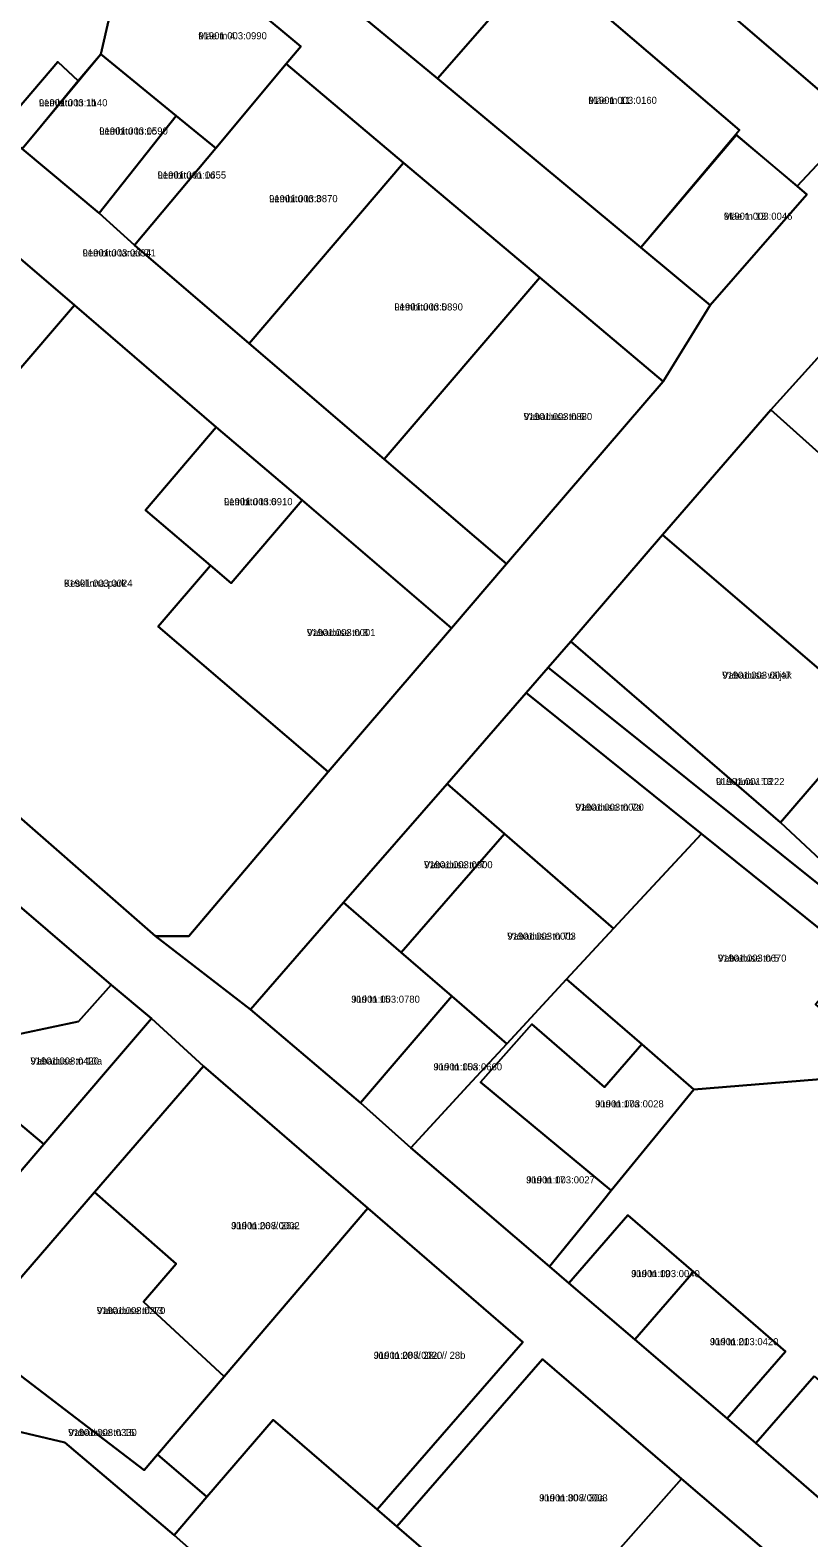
# Model space of a CAD drawing. Extents: x 675810 to 681273, y 6411190 to 6417565.
# Drawn here: x 677993.2 to 678158, y 6415458.6 to 6415777.9 of the extents above; entities that cross this region are included whole.
import ezdxf

# ---------------------------------------------------------------- set-up
doc = ezdxf.new("R2010")
doc.units = 0
for name, color, linetype in [('L_AADRESS', 7, 'Continuous'), ('PIIR', 7, 'Continuous'), ('TUNNUS', 7, 'Continuous')]:
    doc.layers.add(name, color=color, linetype=linetype)

msp = doc.modelspace()

# ---------------------------------------------------------------- linework, layer by layer
at = {"layer": 'PIIR'}
for points in [[(677958.32, 6415851.32), (677965.38, 6415860.08), (677989.04, 6415841.04), (678002.6, 6415830.83), (678017.49, 6415818.31), (678037.27, 6415801.42), (678044.16, 6415797.19), (678064.02, 6415780.43), (678079.45, 6415767.67), (678122.48, 6415731.92), (678137.13, 6415719.66), (678127.15, 6415703.55), (678101.05, 6415725.55), (678072.26, 6415749.82), (678047.39, 6415770.78), (678050.54, 6415774.48), (678021.12, 6415799.06), (677988.86, 6415825.89)], [(678021.12, 6415799.06), (678011.66, 6415787.93), (678008.2, 6415772.88), (678003.37, 6415767.17), (677999.09, 6415771.21), (677986.81, 6415756.9), (677955.66, 6415782.78), (677988.86, 6415825.89)], [(678064.02, 6415780.43), (678078.87, 6415797.95), (678092.14, 6415813.6), (678105.89, 6415797.97), (678101.32, 6415792.73), (678079.45, 6415767.67)], [(678117.15, 6415810.82), (678145.86, 6415788.34), (678140.65, 6415781.96), (678168.13, 6415758.41), (678155.55, 6415744.9), (678142.57, 6415755.89), (678143.29, 6415756.75), (678101.32, 6415792.73), (678105.89, 6415797.97)], [(678169.47, 6415811.87), (678195.91, 6415788.86), (678168.13, 6415758.41), (678140.65, 6415781.96), (678145.86, 6415788.34), (678161.91, 6415807.79), (678164.68, 6415809.53), (678167.52, 6415809.86)], [(677924.58, 6415808.71), (677955.66, 6415782.78), (677986.81, 6415756.9), (677991.57, 6415752.77), (678007.87, 6415739.19), (678015.33, 6415732.38), (678039.55, 6415711.57), (678068.15, 6415687.09), (678094.05, 6415664.94), (678082.36, 6415651.31), (678050.81, 6415678.36), (678032.62, 6415693.85), (678002.6, 6415719.69), (677987.22, 6415732.88), (677983.87, 6415735.76), (677954.46, 6415760.96), (677914.14, 6415795.53)], [(678050.54, 6415774.48), (678047.39, 6415770.78), (678032.53, 6415752.94), (678024.14, 6415759.81), (678008.2, 6415772.88), (678011.66, 6415787.93), (678021.12, 6415799.06)], [(678101.32, 6415792.73), (678143.29, 6415756.75), (678122.48, 6415731.92), (678079.45, 6415767.67)], [(678007.87, 6415739.19), (677991.57, 6415752.77), (678008.2, 6415772.88), (678024.14, 6415759.81)], [(678003.37, 6415767.17), (677995.36, 6415757.42), (677991.57, 6415752.77), (677986.81, 6415756.9), (677999.09, 6415771.21)], [(678072.26, 6415749.82), (678039.55, 6415711.57), (678015.33, 6415732.38), (678032.53, 6415752.94), (678047.39, 6415770.78)], [(678032.53, 6415752.94), (678015.33, 6415732.38), (678007.87, 6415739.19), (678024.14, 6415759.81)], [(678142.65, 6415755.69), (678155.55, 6415744.9), (678157.55, 6415743.14), (678137.13, 6415719.66), (678122.48, 6415731.92)], [(678101.05, 6415725.55), (678068.15, 6415687.09), (678039.55, 6415711.57), (678072.26, 6415749.82)], [(678002.6, 6415719.69), (677976.46, 6415689.19), (677950.55, 6415658.97), (677937.14, 6415670.49), (677939.05, 6415672.69), (677942.18, 6415680.3), (677987.22, 6415732.88)], [(678127.15, 6415703.55), (678094.05, 6415664.94), (678068.15, 6415687.09), (678101.05, 6415725.55)], [(678149.93, 6415697.54), (678176.25, 6415726.67), (678226.09, 6415683.28), (678209.55, 6415664.67), (678199.42, 6415653.2)], [(678002.6, 6415719.69), (678032.62, 6415693.85), (678017.67, 6415676.27), (678031.38, 6415664.55), (678020.32, 6415651.64), (678056.29, 6415620.89), (678026.78, 6415586.06), (678019.75, 6415586.05), (677944.51, 6415651.9), (677950.55, 6415658.97), (677976.46, 6415689.19)], [(678149.93, 6415697.54), (678199.42, 6415653.2), (678202.51, 6415650.44), (678199.77, 6415647.44), (678204.98, 6415642.68), (678185.94, 6415620.54), (678171.56, 6415632.89), (678127.06, 6415671.02)], [(678050.81, 6415678.36), (678035.76, 6415660.8), (678031.38, 6415664.55), (678017.67, 6415676.27), (678032.62, 6415693.85)], [(678050.81, 6415678.36), (678082.36, 6415651.31), (678056.29, 6415620.89), (678020.32, 6415651.64), (678031.38, 6415664.55), (678035.76, 6415660.8)], [(678127.06, 6415671.02), (678171.56, 6415632.89), (678151.99, 6415610.15), (678107.63, 6415648.47)], [(678107.63, 6415648.47), (678151.99, 6415610.15), (678175.26, 6415588.39), (678171.75, 6415587.65), (678102.82, 6415642.96)], [(678098.17, 6415637.56), (678102.82, 6415642.96), (678171.75, 6415587.65), (678186.99, 6415575.28), (678192.63, 6415569.68), (678212.04, 6415550.8), (678212.55, 6415551.27), (678236.61, 6415527.43), (678236.29, 6415527.07), (678244.28, 6415519.15), (678243.42, 6415518.28), (678252.93, 6415507.94), (678255.14, 6415506.85), (678268.24, 6415492.75), (678265.34, 6415490.55), (678245.76, 6415508.69), (678229.11, 6415524.4), (678212.62, 6415540.4), (678185.22, 6415567.57), (678168, 6415581.41), (678135.27, 6415607.73)], [(678098.17, 6415637.56), (678135.27, 6415607.73), (678116.66, 6415587.67), (678093.63, 6415607.71), (678081.44, 6415618.31)], [(678180.57, 6415589.51), (678175.26, 6415588.39), (678151.99, 6415610.15), (678171.56, 6415632.89), (678185.94, 6415620.54), (678183.14, 6415617.25), (678196.51, 6415605.43)], [(678093.63, 6415607.71), (678071.73, 6415582.6), (678059.53, 6415593.19), (678081.44, 6415618.31)], [(678093.63, 6415607.71), (678116.66, 6415587.67), (678106.73, 6415576.96), (678094.07, 6415563.27), (678082.45, 6415573.33), (678071.73, 6415582.6)], [(678106.73, 6415576.96), (678116.66, 6415587.67), (678135.27, 6415607.73), (678168, 6415581.41), (678159.4, 6415571.56), (678176.04, 6415557.04), (678133.69, 6415553.59), (678122.65, 6415563.18)], [(677949.24, 6415526.71), (677933.66, 6415540.22), (677965.56, 6415577.72), (677983.48, 6415598.78), (678010.38, 6415575.72), (678003.47, 6415567.95), (677979.39, 6415562.89), (677976.02, 6415558.85), (677960.12, 6415539.77)], [(678039.87, 6415570.55), (678059.53, 6415593.19), (678071.73, 6415582.6), (678082.45, 6415573.33), (678063.1, 6415550.73)], [(678010.38, 6415575.72), (678018.89, 6415568.59), (677996.11, 6415542.02), (677976.02, 6415558.85), (677979.39, 6415562.89), (678003.47, 6415567.95)], [(678106.73, 6415576.96), (678122.65, 6415563.18), (678114.76, 6415554.09), (678099.41, 6415567.42), (678088.54, 6415555.15), (678116.2, 6415532.17), (678114.54, 6415530.12), (678103.1, 6415516.1), (678073.77, 6415541.23), (678085.86, 6415554.38), (678094.07, 6415563.27)], [(678063.1, 6415550.73), (678082.45, 6415573.33), (678094.07, 6415563.27), (678085.86, 6415554.38), (678073.77, 6415541.23)], [(678018.89, 6415568.59), (678029.89, 6415558.54), (678006.85, 6415531.85), (677980.38, 6415501.17), (677968.13, 6415486.99), (677928.73, 6415441.3), (677913.03, 6415423.03), (677895.43, 6415402.54), (677879.19, 6415383.64), (677867.67, 6415393.29), (677889.64, 6415418.81), (677885.15, 6415422.56), (677942.44, 6415488.99), (677947.03, 6415485.15), (677968.7, 6415510.02), (677979.77, 6415522.93), (677996.11, 6415542.02)], [(678122.65, 6415563.18), (678133.69, 6415553.59), (678116.2, 6415532.17), (678088.54, 6415555.15), (678099.41, 6415567.42), (678114.76, 6415554.09)], [(677996.11, 6415542.02), (677979.77, 6415522.93), (677960.12, 6415539.77), (677976.02, 6415558.85)], [(678029.89, 6415558.54), (678064.7, 6415528.45), (678034.28, 6415492.8), (678017.21, 6415508.63), (678024.12, 6415516.64), (678006.85, 6415531.85)], [(678017.36, 6415472.95), (677980.38, 6415501.17), (678006.85, 6415531.85), (678024.12, 6415516.64), (678017.21, 6415508.63), (678034.28, 6415492.8), (678020.19, 6415476.3)], [(678030.59, 6415467.34), (678020.19, 6415476.3), (678034.28, 6415492.8), (678064.7, 6415528.45), (678097.47, 6415500.09), (678066.65, 6415464.64), (678044.62, 6415483.63)], [(678119.73, 6415526.98), (678133.61, 6415514.96), (678121.2, 6415500.63), (678107.23, 6415512.56)], [(678140.71, 6415483.9), (678121.2, 6415500.63), (678133.61, 6415514.96), (678153.04, 6415498.13)], [(678030.59, 6415467.34), (678023.7, 6415459.23), (678000.6, 6415478.81), (677983.79, 6415482.8), (677976.68, 6415479.77), (677968.13, 6415486.99), (677980.38, 6415501.17), (678017.36, 6415472.95), (678020.19, 6415476.3)], [(678101.64, 6415496.5), (678131.07, 6415471.16), (678099.98, 6415435.92), (678070.82, 6415461.05)], [(678159.11, 6415492.87), (678175.08, 6415479.02), (678169.65, 6415472.82), (678162.82, 6415464.74), (678146.81, 6415478.68)], [(677968.13, 6415486.99), (677976.68, 6415479.77), (677983.79, 6415482.8), (678000.6, 6415478.81), (678023.7, 6415459.23), (678029.87, 6415453.73), (678024.65, 6415447.54), (678032.24, 6415441.38), (678011.23, 6415415.93), (678018.43, 6415409.23), (677966.75, 6415350.05), (677934.44, 6415377.93), (677947.73, 6415393.51), (677948.93, 6415392.45), (677964.97, 6415411.06), (677928.73, 6415441.3)], [(678024.65, 6415447.54), (678029.87, 6415453.73), (678023.7, 6415459.23), (678030.59, 6415467.34), (678044.62, 6415483.63), (678066.65, 6415464.64), (678070.82, 6415461.05), (678099.98, 6415435.92), (678105.17, 6415431.39), (678080.12, 6415402.19), (678032.24, 6415441.38)], [(678099.98, 6415435.92), (678131.07, 6415471.16), (678151.94, 6415453.26), (678138.38, 6415437.18), (678131.41, 6415442.85), (678105.17, 6415431.39)]]:
    msp.add_lwpolyline(points, close=True, dxfattribs=at)
for points in [[(678276.58, 6415835.21), (678213.72, 6415768.23), (678176.25, 6415726.67), (678149.93, 6415697.54), (678127.06, 6415671.02), (678107.63, 6415648.47), (678102.82, 6415642.96), (678098.17, 6415637.56), (678081.44, 6415618.31), (678059.53, 6415593.19), (678039.87, 6415570.55), (678019.75, 6415586.05), (678026.78, 6415586.06), (678056.29, 6415620.89), (678082.36, 6415651.31), (678094.05, 6415664.94), (678127.15, 6415703.55), (678137.13, 6415719.66), (678157.55, 6415743.14), (678155.55, 6415744.9), (678168.13, 6415758.41), (678195.91, 6415788.86)], [(677790.48, 6415783.86), (677837.71, 6415743.69), (677839.54, 6415742.61), (677843.93, 6415741.95), (677859.17, 6415725.55), (677869.45, 6415716.69), (677902.53, 6415688.09), (677926.18, 6415667.7), (677944.51, 6415651.9), (678019.75, 6415586.05), (678039.87, 6415570.55), (678063.1, 6415550.73), (678073.77, 6415541.23), (678103.1, 6415516.1), (678107.23, 6415512.56), (678121.2, 6415500.63), (678140.71, 6415483.9), (678146.81, 6415478.68), (678162.82, 6415464.74)], [(678181.09, 6415427.91), (678151.94, 6415453.26), (678131.07, 6415471.16), (678101.64, 6415496.5), (678070.82, 6415461.05), (678066.65, 6415464.64), (678097.47, 6415500.09), (678064.7, 6415528.45), (678029.89, 6415558.54), (678018.89, 6415568.59), (678010.38, 6415575.72), (677983.48, 6415598.78), (677963.18, 6415616.09), (677950.54, 6415626.89), (677940.26, 6415635.63), (677918.32, 6415654.28), (677884.76, 6415683.55), (677867.43, 6415698.31), (677831.96, 6415720.82), (677830.81, 6415727.16), (677801.5, 6415752.2)], [(678159.11, 6415492.87), (678146.81, 6415478.68), (678140.71, 6415483.9), (678153.04, 6415498.13), (678133.61, 6415514.96), (678119.73, 6415526.98), (678107.23, 6415512.56), (678103.1, 6415516.1), (678114.54, 6415530.12), (678116.2, 6415532.17), (678133.69, 6415553.59), (678176.04, 6415557.04)]]:
    msp.add_lwpolyline(points, dxfattribs=at)

# ---------------------------------------------------------------- texts
at = {"layer": 'L_AADRESS'}
for s, p in [('Mäe tn 4', (678028.82, 6415776)), ('Lembitu tn 1b', (677995.09, 6415761.82)), ('Mäe tn 11', (678111.34, 6415762.33)), ('Lembitu tn 1c', (678007.86, 6415755.83)), ('Lembitu tn 1d', (678020.2, 6415746.51)), ('Lembitu tn 3', (678043.79, 6415741.5)), ('Mäe tn 13', (678140.01, 6415737.78)), ('Lembitu tänav T1', (678004.33, 6415730.01)), ('Lembitu tn 5', (678070.3, 6415718.57)), ('Vabaduse tn 6', (678097.65, 6415695.36)), ('Lembitu tn 6', (678034.25, 6415677.33)), ('Kesklinna park', (678000.4, 6415660.05)), ('Vabaduse tn 8', (678051.8, 6415649.62)), ('Vabaduse väljak', (678139.67, 6415640.58)), ('Uus tänav T3', (678138.34, 6415618.06)), ('Vabaduse tn 7a', (678108.59, 6415612.62)), ('Vabaduse tn 7', (678076.58, 6415600.45)), ('Vabaduse tn 7b', (678094.19, 6415585.31)), ('Vabaduse tn 5', (678138.75, 6415580.66)), ('Jüri tn 15', (678061.19, 6415571.96)), ('Vabaduse tn 10a', (677993.3, 6415558.87)), ('Jüri tn 15a', (678078.59, 6415557.64)), ('Jüri tn 17a', (678112.79, 6415549.8)), ('Jüri tn 17', (678098.21, 6415533.7)), ('Jüri tn 26 // 26a', (678035.78, 6415524)), ('Jüri tn 19', (678120.42, 6415513.84)), ('Vabaduse tn 13', (678007.33, 6415506.02)), ('Jüri tn 21', (678137.07, 6415499.43)), ('Jüri tn 28 // 28a // 28b', (678065.93, 6415496.54)), ('Vabaduse tn 15', (678001.3, 6415480.2)), ('Jüri tn 30 // 30a', (678100.95, 6415466.36))]:
    msp.add_text(s, height=1.5, dxfattribs=at).set_placement(p)
at = {"layer": 'TUNNUS'}
for s, p in [('91901:003:0990', (678028.82, 6415776)), ('91901:003:1140', (677995.09, 6415761.82)), ('91901:003:0160', (678111.34, 6415762.33)), ('91901:003:0590', (678007.86, 6415755.83)), ('91901:001:0655', (678020.2, 6415746.51)), ('91901:003:0870', (678043.79, 6415741.5)), ('91901:003:0046', (678140.01, 6415737.78)), ('91901:003:0034', (678004.33, 6415730.01)), ('91901:003:0890', (678070.3, 6415718.57)), ('91901:003:0880', (678097.65, 6415695.36)), ('91901:003:0910', (678034.25, 6415677.33)), ('91901:003:0024', (678000.4, 6415660.05)), ('91901:003:0001', (678051.8, 6415649.62)), ('91901:003:0047', (678139.67, 6415640.58)), ('91901:001:0222', (678138.34, 6415618.06)), ('91901:003:0020', (678108.59, 6415612.62)), ('91901:003:0900', (678076.58, 6415600.45)), ('91901:003:0003', (678094.19, 6415585.31)), ('91901:003:0670', (678138.75, 6415580.66)), ('91901:003:0780', (678061.19, 6415571.96)), ('91901:008:0420', (677993.3, 6415558.87)), ('91901:003:0660', (678078.59, 6415557.64)), ('91901:003:0028', (678112.79, 6415549.8)), ('91901:003:0027', (678098.21, 6415533.7)), ('91901:008:0002', (678035.78, 6415524)), ('91901:003:0040', (678120.42, 6415513.84)), ('91901:008:0270', (678007.33, 6415506.02)), ('91901:003:0420', (678137.07, 6415499.43)), ('91901:008:0020', (678065.93, 6415496.54)), ('91901:008:0330', (678001.3, 6415480.2)), ('91901:008:0003', (678100.95, 6415466.36))]:
    msp.add_text(s, height=1.5, dxfattribs=at).set_placement(p)

doc.saveas('drawing.dxf')
